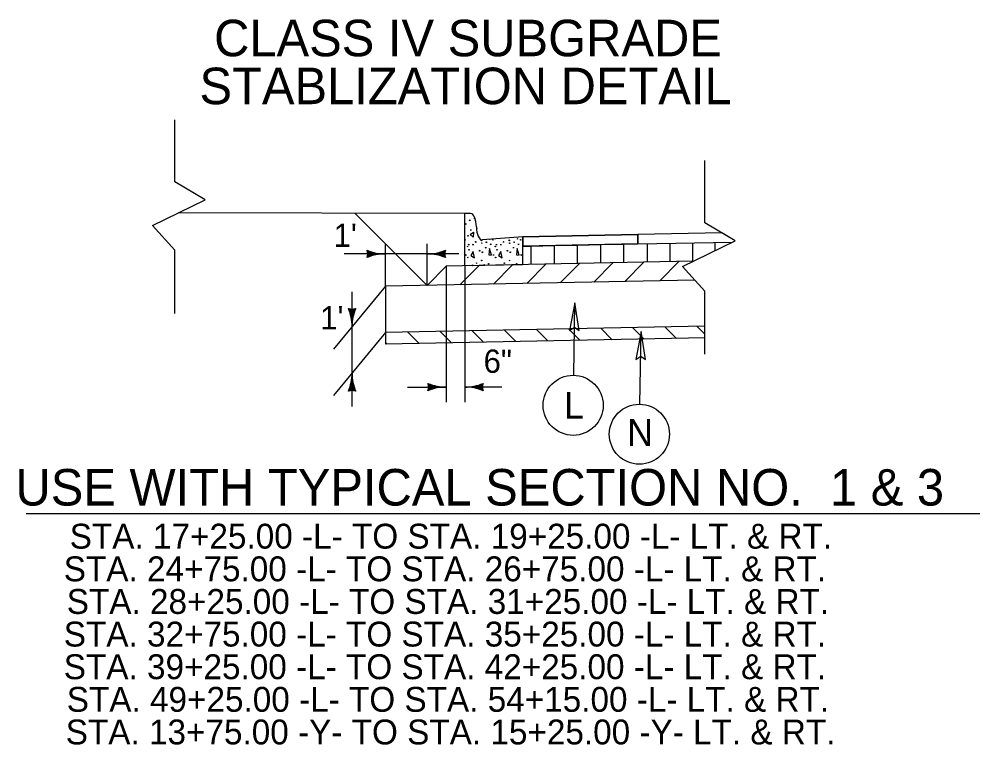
# Model space of a CAD drawing. Extents: x 2176156 to 2177167, y 76401 to 76644.
# Drawn here: x 2176576.79 to 2176618.23, y 76550.64 to 76581.95 of the extents above; entities that cross this region are included whole.
import ezdxf

# ---------------------------------------------------------------- set-up
doc = ezdxf.new("R2010")
doc.units = 0
for name, color, linetype in [('Exist Building Metal Canopy', 7, 'Continuous'), ('Exist Roads Curbs', 7, 'Continuous'), ('Exist Roads EOP Other', 7, 'Continuous'), ('Exist Roads Soil', 7, 'Continuous'), ('Exist Vegetation Woods Line', 7, 'Continuous'), ('Model Boundary Lines Text', 7, 'Continuous'), ('PH Exist DTM Breakline', 7, 'Continuous'), ('Prop North Arrow NAD83 for Plan Sheets CELL', 7, 'Continuous')]:
    doc.layers.add(name, color=color, linetype=linetype)

msp = doc.modelspace()

# ---------------------------------------------------------------- linework, layer by layer
at = {"layer": 'Exist Roads Curbs'}
for p, q in [((2176603.484, 76572.659), (2176598.516, 76572.559)), ((2176598.516, 76572.559), (2176598.516, 76572.156)), ((2176607.111, 76572.731), (2176603.484, 76572.659)), ((2176603.484, 76572.256), (2176603.484, 76572.659)), ((2176603.484, 76572.659), (2176603.484, 76572.256)), ((2176603.484, 76572.256), (2176607.565, 76572.337))]:
    msp.add_line(p, q, dxfattribs=at)
for points in [[(2176607.565, 76572.337), (2176607.68, 76572.394), (2176607.111, 76572.731)], [(2176598.516, 76572.156), (2176598.882, 76572.164), (2176599.882, 76572.184)], [(2176599.882, 76572.184), (2176600.882, 76572.204), (2176601.882, 76572.224), (2176602.882, 76572.244), (2176603.484, 76572.256)]]:
    msp.add_lwpolyline(points, dxfattribs=at)
at = {"layer": 'Exist Roads EOP Other'}
for p, q in [((2176596.016, 76573.567), (2176583.658, 76573.592)), ((2176605.411, 76571.283), (2176606.376, 76570.22))]:
    msp.add_line(p, q, dxfattribs=at)
for points in [[(2176583.511, 76569.255), (2176583.511, 76571.984), (2176582.545, 76573.047), (2176584.815, 76574.158), (2176583.511, 76574.931), (2176583.511, 76577.612)], [(2176606.376, 76567.491), (2176606.376, 76570.22), (2176605.411, 76571.283), (2176607.68, 76572.394), (2176606.376, 76573.167), (2176606.376, 76575.848)]]:
    msp.add_lwpolyline(points, dxfattribs=at)
at = {"layer": 'Exist Roads Soil'}
for p, q in [((2176591.275, 76573.577), (2176594.389, 76570.463)), ((2176598.516, 76572.559), (2176603.484, 76572.659)), ((2176603.484, 76572.256), (2176603.484, 76572.659)), ((2176603.484, 76572.256), (2176598.516, 76572.156)), ((2176605.861, 76571.503), (2176595.216, 76571.29)), ((2176595.216, 76571.29), (2176594.389, 76570.463)), ((2176605.945, 76570.694), (2176592.589, 76570.427)), ((2176592.589, 76570.427), (2176592.589, 76567.927)), ((2176606.376, 76568.702), (2176592.589, 76568.427)), ((2176606.386, 76568.203), (2176592.589, 76567.927))]:
    msp.add_line(p, q, dxfattribs=at)
at = {"layer": 'Model Boundary Lines Text'}
for p, q in [((2176596.016, 76571.306), (2176596.016, 76573.567)), ((2176596.266, 76573.567), (2176596.016, 76573.567)), ((2176598.516, 76572.559), (2176596.773, 76572.425)), ((2176598.516, 76571.356), (2176598.516, 76572.559)), ((2176598.882, 76571.364), (2176598.882, 76572.164)), ((2176599.882, 76571.384), (2176599.882, 76572.184)), ((2176600.882, 76571.404), (2176600.882, 76572.204)), ((2176601.882, 76571.424), (2176601.882, 76572.224)), ((2176602.882, 76571.444), (2176602.882, 76572.244)), ((2176603.901, 76571.464), (2176603.901, 76572.264)), ((2176604.877, 76571.484), (2176604.877, 76572.284)), ((2176605.855, 76571.503), (2176605.855, 76572.303)), ((2176606.817, 76571.972), (2176606.817, 76572.323)), ((2176595.804, 76570.491), (2176596.632, 76571.319)), ((2176598.516, 76571.356), (2176596.016, 76571.306)), ((2176597.248, 76570.52), (2176598.075, 76571.347)), ((2176598.691, 76570.549), (2176599.518, 76571.376)), ((2176600.134, 76570.578), (2176600.961, 76571.405)), ((2176601.577, 76570.607), (2176602.404, 76571.434)), ((2176602.915, 76570.634), (2176603.743, 76571.462)), ((2176604.426, 76570.664), (2176605.253, 76571.491)), ((2176593.563, 76568.446), (2176594.054, 76567.956)), ((2176594.95, 76568.474), (2176595.44, 76567.984)), ((2176596.336, 76568.502), (2176596.827, 76568.011)), ((2176597.723, 76568.529), (2176598.213, 76568.039)), ((2176599.109, 76568.557), (2176599.6, 76568.067)), ((2176600.496, 76568.585), (2176600.986, 76568.095)), ((2176601.882, 76568.613), (2176602.373, 76568.122)), ((2176603.269, 76568.64), (2176603.759, 76568.15)), ((2176604.655, 76568.668), (2176605.146, 76568.178)), ((2176606.042, 76568.696), (2176606.376, 76568.361)), ((2176592.589, 76568.007), (2176592.667, 76567.928)), ((2176577.087, 76560.62), (2176618.235, 76560.62))]:
    msp.add_line(p, q, dxfattribs=at)
for centre, start_param, end_param in [((2176596.266, 76572.968), 4.760509, 6.283184), ((2176596.766, 76573.025), 1.618916, 3.173504)]:
    msp.add_ellipse(centre, major_axis=(0, 0.6), ratio=0.416667, start_param=start_param, end_param=end_param, dxfattribs=at)
at = {"layer": 'PH Exist DTM Breakline'}
for p, q in [((2176596.251, 76572.655), (2176596.399, 76572.758)), ((2176596.383, 76572.55), (2176596.251, 76572.655)), ((2176596.399, 76572.758), (2176596.383, 76572.55)), ((2176596.372, 76571.921), (2176596.273, 76571.748)), ((2176596.273, 76571.748), (2176596.432, 76571.657)), ((2176596.432, 76571.657), (2176596.372, 76571.921)), ((2176597.084, 76572.05), (2176597.051, 76571.789)), ((2176597.051, 76571.789), (2176597.166, 76571.774)), ((2176597.166, 76571.774), (2176597.084, 76572.05)), ((2176597.571, 76571.921), (2176597.472, 76571.748)), ((2176597.472, 76571.748), (2176597.631, 76571.657)), ((2176597.631, 76571.657), (2176597.571, 76571.921)), ((2176598.283, 76572.05), (2176598.25, 76571.789)), ((2176598.25, 76571.789), (2176598.366, 76571.774)), ((2176598.366, 76571.774), (2176598.283, 76572.05))]:
    msp.add_line(p, q, dxfattribs=at)
for centre in [(2176596.055, 76573.115), (2176596.229, 76573.273), (2176596.437, 76573.352), (2176596.152, 76572.603), (2176596.278, 76572.852), (2176596.536, 76572.918), (2176596.027, 76572.432), (2176596.132, 76572.144), (2176596.185, 76572.223), (2176596.372, 76572.223), (2176596.487, 76572.34), (2176596.733, 76572.405), (2176596.75, 76572.289), (2176596.947, 76572.326), (2176597.134, 76572.236), (2176597.227, 76572.432), (2176597.331, 76572.144), (2176597.385, 76572.223), (2176597.571, 76572.223), (2176597.686, 76572.34), (2176597.933, 76572.405), (2176597.949, 76572.289), (2176598.146, 76572.326), (2176598.289, 76572.471), (2176598.333, 76572.236), (2176598.426, 76572.432), (2176596.055, 76571.776), (2176596.202, 76572), (2176596.657, 76571.96), (2176596.777, 76571.894), (2176596.92, 76572.092), (2176597.254, 76571.776), (2176597.401, 76572), (2176597.856, 76571.96), (2176597.976, 76571.894), (2176598.119, 76572.092), (2176598.453, 76571.776), (2176596.147, 76571.67), (2176596.355, 76571.329), (2176596.52, 76571.421), (2176596.744, 76571.539), (2176596.854, 76571.342), (2176597.051, 76571.394), (2176597.346, 76571.67), (2176597.719, 76571.421), (2176597.944, 76571.539), (2176598.251, 76571.394)]:
    msp.add_ellipse(centre, major_axis=(0, 0.0185), ratio=0.416667, dxfattribs=at)
msp.add_ellipse((2176597.09, 76572.471), major_axis=(0, 0.0185), ratio=0.416667, start_param=1.494213, end_param=4.872315, dxfattribs=at)
at = {"layer": 'Prop North Arrow NAD83 for Plan Sheets CELL'}
for p, q in [((2176592.589, 76570.427), (2176592.589, 76572.228)), ((2176594.389, 76570.463), (2176594.389, 76572.264)), ((2176595.759, 76571.823), (2176590.807, 76571.823)), ((2176596.016, 76571.306), (2176596.016, 76565.422)), ((2176595.216, 76571.29), (2176595.216, 76565.422)), ((2176592.589, 76570.427), (2176590.355, 76567.717)), ((2176591.152, 76565.234), (2176591.152, 76570.185)), ((2176600.714, 76566.586), (2176600.77, 76569.719)), ((2176592.589, 76568.427), (2176590.355, 76565.717)), ((2176603.572, 76565.338), (2176603.628, 76568.47)), ((2176593.549, 76566.078), (2176595.216, 76566.078)), ((2176597.616, 76566.078), (2176596.016, 76566.078))]:
    msp.add_line(p, q, dxfattribs=at)
for points in [[(2176600.956, 76568.515), (2176600.77, 76569.719), (2176600.535, 76568.516), (2176600.751, 76568.665)], [(2176603.813, 76567.267), (2176603.628, 76568.47), (2176603.393, 76567.267), (2176603.609, 76567.417)]]:
    msp.add_lwpolyline(points, close=True, dxfattribs=at)
for centre in [(2176600.691, 76565.29), (2176603.548, 76564.042)]:
    msp.add_circle(centre, 1.296, dxfattribs=at)
for centre, radius, start, end in [((2176591.38, 76571.823), 0.448, 339.2343, 20.766), ((2176592.563, 76573.738), 1.915, 246.4848, 270.7622), ((2176592.563, 76569.908), 1.915, 89.2381, 113.5155), ((2176592.563, 76573.738), 1.942, 247.1893, 260.4638), ((2176592.563, 76569.908), 1.942, 99.5365, 112.811), ((2176592.563, 76573.738), 1.969, 247.7696, 256.6115), ((2176592.563, 76569.908), 1.969, 103.3888, 112.2307), ((2176592.563, 76573.738), 1.995, 248.2502, 253.7031), ((2176592.563, 76569.908), 1.995, 106.2972, 111.7501), ((2176592.563, 76573.738), 2.022, 248.6472, 251.2913), ((2176592.563, 76569.908), 2.022, 108.709, 111.3531), ((2176594.414, 76573.738), 1.915, 269.2382, 293.5156), ((2176594.414, 76569.908), 1.915, 66.4849, 90.7623), ((2176594.414, 76573.738), 1.942, 279.5367, 292.8111), ((2176594.414, 76569.908), 1.942, 67.1895, 80.4639), ((2176594.414, 76573.738), 1.969, 283.389, 292.2308), ((2176594.414, 76569.908), 1.969, 67.7698, 76.6116), ((2176594.414, 76573.738), 1.995, 286.2973, 291.7503), ((2176594.414, 76569.908), 1.995, 68.2503, 73.7032), ((2176594.414, 76573.738), 2.022, 288.7091, 291.3532), ((2176594.414, 76569.908), 2.022, 68.6473, 71.2914), ((2176595.597, 76571.823), 0.448, 159.2344, 200.7661), ((2176591.152, 76569.893), 0.448, 249.2342, 290.7658), ((2176589.237, 76568.709), 1.915, 359.2379, 23.5154), ((2176589.237, 76568.709), 1.942, 9.5364, 22.8108), ((2176589.237, 76568.709), 1.969, 13.3887, 22.2305), ((2176589.237, 76568.709), 1.995, 16.2971, 21.75), ((2176589.237, 76568.709), 2.022, 18.7088, 21.3529), ((2176593.067, 76568.709), 1.915, 156.4846, 180.7621), ((2176593.067, 76568.709), 1.942, 157.1892, 170.4636), ((2176593.067, 76568.709), 1.969, 157.7695, 166.6113), ((2176593.067, 76568.709), 1.995, 158.25, 163.7029), ((2176593.067, 76568.709), 2.022, 158.6471, 161.2912), ((2176589.237, 76566.658), 1.915, 336.4846, 0.7621), ((2176589.237, 76566.658), 1.942, 337.1892, 350.4636), ((2176593.067, 76566.658), 1.915, 179.2379, 203.5153), ((2176593.067, 76566.658), 1.942, 189.5364, 202.8108), ((2176591.152, 76565.475), 0.448, 69.2342, 110.7658), ((2176589.237, 76566.658), 1.969, 337.7695, 346.6113), ((2176589.237, 76566.658), 1.995, 338.25, 343.7029), ((2176589.237, 76566.658), 2.022, 338.6471, 341.2912), ((2176593.067, 76566.658), 1.969, 193.3887, 202.2305), ((2176593.067, 76566.658), 1.995, 196.2971, 201.75), ((2176593.067, 76566.658), 2.022, 198.7088, 201.3529), ((2176594.007, 76566.078), 0.448, 339.2343, 20.766), ((2176595.19, 76567.993), 1.915, 246.4848, 270.7622), ((2176595.191, 76564.162), 1.915, 89.2381, 113.5155), ((2176595.19, 76567.993), 1.942, 247.1893, 260.4638), ((2176595.191, 76564.162), 1.942, 99.5365, 112.811), ((2176595.19, 76567.993), 1.969, 247.7696, 256.6115), ((2176595.191, 76564.162), 1.969, 103.3888, 112.2307), ((2176595.19, 76567.993), 1.995, 248.2502, 253.7031), ((2176595.191, 76564.162), 1.995, 106.2972, 111.7501), ((2176595.19, 76567.993), 2.022, 248.6472, 251.2913), ((2176595.191, 76564.162), 2.022, 108.709, 111.3531), ((2176596.041, 76567.993), 1.915, 269.2382, 293.5156), ((2176596.042, 76564.162), 1.915, 66.4849, 90.7623), ((2176596.041, 76567.993), 1.942, 279.5367, 292.8111), ((2176596.042, 76564.162), 1.942, 67.1895, 80.4639), ((2176596.041, 76567.993), 1.969, 283.389, 292.2308), ((2176596.042, 76564.162), 1.969, 67.7698, 76.6116), ((2176596.041, 76567.993), 1.995, 286.2973, 291.7503), ((2176596.042, 76564.162), 1.995, 68.2503, 73.7032), ((2176596.041, 76567.993), 2.022, 288.7091, 291.3532), ((2176596.042, 76564.162), 2.022, 68.6473, 71.2914), ((2176597.225, 76566.077), 0.448, 159.2344, 200.7661)]:
    msp.add_arc(centre, radius, start, end, dxfattribs=at)

# ---------------------------------------------------------------- texts
at = {"layer": 'Exist Building Metal Canopy'}
msp.add_text('USE WITH TYPICAL SECTION NO.  1 & 3', height=1.5766, rotation=0, dxfattribs=at).set_placement((2176576.63, 76560.965))
at = {"layer": 'Exist Vegetation Woods Line'}
for s, height, p in [('CLASS IV SUBGRADE ', 1.5766, (2176585.2, 76580.351)), ('STABLIZATION DETAIL', 1.5766, (2176584.57, 76578.284)), ('STA. 17+25.00 -L- TO STA. 19+25.00 -L- LT. & RT.', 1.0742, (2176578.971, 76559.106)), ('STA. 24+75.00 -L- TO STA. 26+75.00 -L- LT. & RT.', 1.0742, (2176578.714, 76557.697)), ('STA. 28+25.00 -L- TO STA. 31+25.00 -L- LT. & RT.', 1.0742, (2176578.843, 76556.289)), ('STA. 32+75.00 -L- TO STA. 35+25.00 -L- LT. & RT.', 1.0742, (2176578.714, 76554.881)), ('STA. 39+25.00 -L- TO STA. 42+25.00 -L- LT. & RT.', 1.0742, (2176578.714, 76553.473)), ('STA. 49+25.00 -L- TO STA. 54+15.00 -L- LT. & RT.', 1.0742, (2176578.843, 76552.065)), ('STA. 13+75.00 -Y- TO STA. 15+25.00 -Y- LT. & RT.', 1.0742, (2176578.799, 76550.657))]:
    msp.add_text(s, height=height, dxfattribs=at).set_placement(p)
at = {"layer": 'Prop North Arrow NAD83 for Plan Sheets CELL'}
for s, height, rotation, p in [("1'", 1.0064, 0.0002, (2176590.353, 76572.124)), ("1'", 1.0064, 0.0002, (2176589.776, 76568.563)), ('6"', 1.0064, 0.0002, (2176596.826, 76566.691)), ('L', 1.16, 0, (2176600.296, 76564.71)), ('N', 1.16, 0, (2176603.02, 76563.534))]:
    msp.add_text(s, height=height, rotation=rotation, dxfattribs=at).set_placement(p)

doc.saveas('drawing.dxf')
